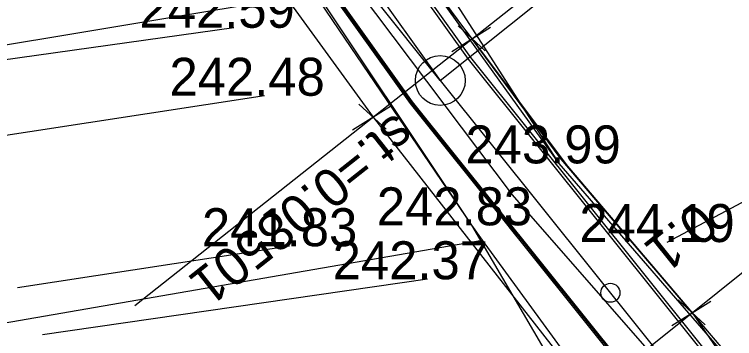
# Model space of a CAD drawing. Extents: x -601754 to -601440, y -1201912 to -1200862.
# Drawn here: x -601633.19 to -601595.26, y -1200981.82 to -1200964.76 of the extents above; entities that cross this region are included whole.
import ezdxf

# ---------------------------------------------------------------- set-up
doc = ezdxf.new("R2010")
doc.units = 0
for name, color, linetype in [('Hranice parcel', 7, 'Continuous'), ('u_drén', 7, 'Continuous'), ('u_hrany', 7, 'Continuous'), ('u_krizky', 7, 'Continuous'), ('u_návrh', 7, 'Continuous'), ('u_oblouky', 7, 'Continuous'), ('u_osa', 7, 'Continuous'), ('u_pricne_cesta', 7, 'Continuous'), ('u_sklony', 7, 'Continuous'), ('u_staniceni', 7, 'Continuous'), ('u_terénní úpravy', 7, 'Continuous'), ('u_vyska', 7, 'Continuous')]:
    doc.layers.add(name, color=color, linetype=linetype)

msp = doc.modelspace()

# ---------------------------------------------------------------- linework, layer by layer
at = {"layer": 'Hranice parcel'}
msp.add_line((-601608.55, -1200976.64), (-601598.35, -1200990.64), dxfattribs=at)
for points in [[(-601589.41, -1200989.76), (-601594.55, -1200983.92), (-601604.39, -1200972.37), (-601611.28, -1200963.08)], [(-601751.585, -1200977.923), (-601676.3, -1200973.45), (-601617.41, -1200963.63)], [(-601617.41, -1200963.63), (-601609.12, -1200975.86), (-601608.55, -1200976.64)], [(-601751.585, -1200994.375), (-601673.71, -1200987.92), (-601608.55, -1200976.64)]]:
    msp.add_lwpolyline(points, dxfattribs=at)
at = {"layer": 'u_drén'}
msp.add_lwpolyline([(-601630.738, -1200933.27), (-601628.676, -1200940.153), (-601624.291, -1200950.498), (-601618.798, -1200960.3), (-601612.295, -1200969.398), (-601587.744, -1201000.039)], dxfattribs=at)
at = {"layer": 'u_hrany'}
for points in [[(-601637.65, -1200892.44), (-601636.56, -1200901.01), (-601634.78, -1200919.25), (-601632.6, -1200928.32), (-601629.33, -1200937.82), (-601624.51, -1200947.91), (-601616.86, -1200961.13), (-601606.97, -1200974.25), (-601596.82, -1200985.88), (-601582.46, -1201002.22), (-601574.49, -1201012.64), (-601569.33, -1201022.81), (-601566.79, -1201038.25), (-601566.21, -1201048.21)], [(-601568.57, -1201015.08), (-601571.45, -1201010.54), (-601577.11, -1201003.42), (-601594.37, -1200984.29), (-601604.5, -1200972.6), (-601614.07, -1200959.31), (-601621.9, -1200946.57), (-601626.39, -1200937.08), (-601629.97, -1200926.48)], [(-601629.33, -1200937.82), (-601626.28, -1200948.41), (-601618.2, -1200962.23), (-601609.12, -1200975.86), (-601600.84, -1200990.01)], [(-601604.5, -1200972.6), (-601610.78, -1200962.81), (-601598.49, -1200956.19)], [(-601621.64, -1200965.46), (-601639.56, -1200967.97)], [(-601620.01, -1200969.04), (-601638.58, -1200971.89)], [(-601598.82, -1200976.74), (-601585.07, -1200969.44)], [(-601618.7, -1200976.96), (-601633.03, -1200979.15)], [(-601611.44, -1200978.7), (-601631.71, -1200981.63)]]:
    msp.add_lwpolyline(points, dxfattribs=at)
at = {"layer": 'u_krizky'}
for p, q in [((-601608.108, -1200965.45), (-601610.161, -1200966.73)), ((-601608.401, -1200966.676), (-601609.828, -1200965.357)), ((-601613.324, -1200969.572), (-601615.376, -1200970.852)), ((-601613.617, -1200970.798), (-601615.043, -1200969.479)), ((-601596.517, -1200979.873), (-601598.57, -1200981.153)), ((-601596.81, -1200981.099), (-601598.237, -1200979.78))]:
    msp.add_line(p, q, dxfattribs=at)
at = {"layer": 'u_návrh'}
for points in [[(-601634.025, -1200887.577), (-601630.185, -1200917.812), (-601628.225, -1200928.505), (-601625.119, -1200938.871), (-601620.896, -1200948.834), (-601615.607, -1200958.274), (-601609.285, -1200967.119), (-601584.73, -1200997.764)], [(-601633.876, -1200887.558), (-601630.036, -1200917.789), (-601628.079, -1200928.47), (-601624.978, -1200938.82), (-601620.761, -1200948.768), (-601615.48, -1200958.194), (-601609.165, -1200967.028), (-601578.723, -1201005.021)], [(-601637.844, -1200888.062), (-601633.991, -1200918.402), (-601631.974, -1200929.408), (-601628.747, -1200940.179), (-601624.358, -1200950.531), (-601618.862, -1200960.341), (-601612.355, -1200969.444), (-601581.832, -1201007.537)], [(-601637.695, -1200888.043), (-601633.842, -1200918.379), (-601631.828, -1200929.372), (-601628.605, -1200940.128), (-601624.223, -1200950.465), (-601618.735, -1200960.26), (-601612.236, -1200969.353), (-601587.617, -1201000.078)]]:
    msp.add_lwpolyline(points, dxfattribs=at)
at = {"layer": 'u_oblouky'}
for q in [(-601580.365, -1200943.882), (-601628.449, -1200946.159)]:
    msp.add_line((-601610.76, -1200968.236), q, dxfattribs=at)
msp.add_circle((-601610.76, -1200968.236), 1.311, dxfattribs=at)
at = {"layer": 'u_osa'}
msp.add_lwpolyline([(-601635.86, -1200887.81), (-601632.013, -1200918.095), (-601630.026, -1200928.939), (-601626.862, -1200939.5), (-601622.56, -1200949.65), (-601617.171, -1200959.267), (-601610.76, -1200968.236), (-601578.672, -1201008.284), (-601575.031, -1201013.469), (-601572.075, -1201019.074), (-601569.852, -1201025.007), (-601568.398, -1201031.174), (-601566.15, -1201044.408), (-601565.576, -1201049.148), (-601565.456, -1201053.922), (-601565.793, -1201058.685), (-601566.228, -1201062.343), (-601567.198, -1201067.854), (-601568.778, -1201073.221), (-601570.948, -1201078.378), (-601573.681, -1201083.261), (-601575.226, -1201085.692), (-601578.132, -1201090.011)], dxfattribs=at)
at = {"layer": 'u_pricne_cesta'}
for points in [[(-601595.458, -1200955.29), (-601611.149, -1200967.692), (-601626.84, -1200980.093)], [(-601583.989, -1200969.663), (-601599.597, -1200982.168), (-601615.204, -1200994.674)]]:
    msp.add_lwpolyline(points, dxfattribs=at)
at = {"layer": 'u_sklony'}
msp.add_line((-601607.148, -1200975.943), (-601604.64, -1200979.072), dxfattribs=at)
at = {"layer": 'u_staniceni'}
msp.add_circle((-601601.804, -1200979.414), 0.5, dxfattribs=at)
at = {"layer": 'u_terénní úpravy'}
for points in [[(-601638.582, -1200888.156), (-601634.493, -1200918.503), (-601632.607, -1200929.56), (-601631.638, -1200933.524), (-601630.127, -1200940.76), (-601625.442, -1200954.325), (-601625.442, -1200954.325), (-601620.62, -1200961.457), (-601614.291, -1200970.175), (-601602.86, -1200984.783)], [(-601623.651, -1200937.04), (-601622.862, -1200939.893), (-601618.936, -1200950.908), (-601615.274, -1200957.893), (-601609.075, -1200966.053), (-601604.07, -1200972.745), (-601597.484, -1200980.476), (-601592.22, -1200988.176), (-601585.958, -1200994.904), (-601578.723, -1201005.021), (-601574.41, -1201008.093), (-601573.524, -1201008.969), (-601571.743, -1201011.837), (-601569.512, -1201016.171), (-601566.023, -1201016.188)]]:
    msp.add_lwpolyline(points, dxfattribs=at)

# ---------------------------------------------------------------- texts
at = {"layer": 'u_pricne_cesta'}
msp.add_text('st.=0.08501', height=2, rotation=218.3223, dxfattribs=at).set_placement((-601613.097, -1200969.904))
at = {"layer": 'u_staniceni'}
msp.add_text('0.1', height=2, rotation=218.7034, dxfattribs=at).set_placement((-601597.234, -1200974.578))
at = {"layer": 'u_vyska'}
for s, p in [('242.59', (-601626.6, -1200965.46)), ('242.48', (-601625.022, -1200969.04)), ('243.99', (-601609.435, -1200972.6)), ('242.83', (-601614.104, -1200975.86)), ('241.83', (-601623.313, -1200976.96)), ('244.19', (-601603.436, -1200976.74)), ('242.37', (-601616.429, -1200978.7))]:
    msp.add_text(s, height=2, dxfattribs=at).set_placement(p)

doc.saveas('drawing.dxf')
